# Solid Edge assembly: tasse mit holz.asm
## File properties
Author: Dieter
Template: Normal.asm
Last saved by: Dieter
Revision: 2
Application: Solid Edge
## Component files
Spiegelecke Boden schwarz.par
Tasse.par
